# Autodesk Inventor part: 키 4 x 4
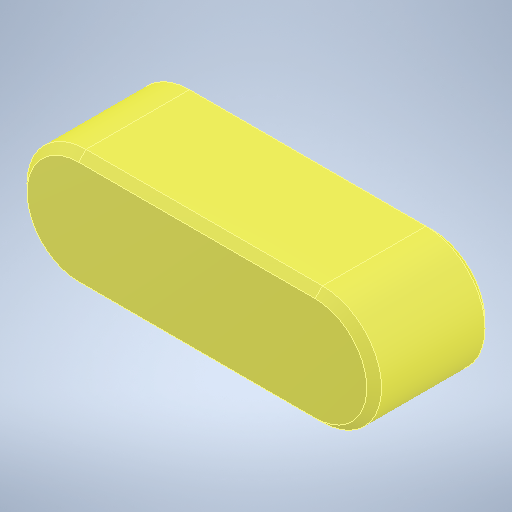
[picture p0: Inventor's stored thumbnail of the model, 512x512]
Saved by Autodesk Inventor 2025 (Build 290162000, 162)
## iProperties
Created: 2024-08
Part Number: 키 4 x 4
Material: 강철, 연강
Description: 키 및 해당 키홈
Document SubType Name: Modeling
Designer: deana
Density: 7.86 g/cm^3
Appearance: 기본값
Author: jhkim
Sending System: Autodesk Inventor 2025
Preprocessor: ST-DEVELOPER v20
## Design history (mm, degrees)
feature "Solid1"
node "솔리드1"
